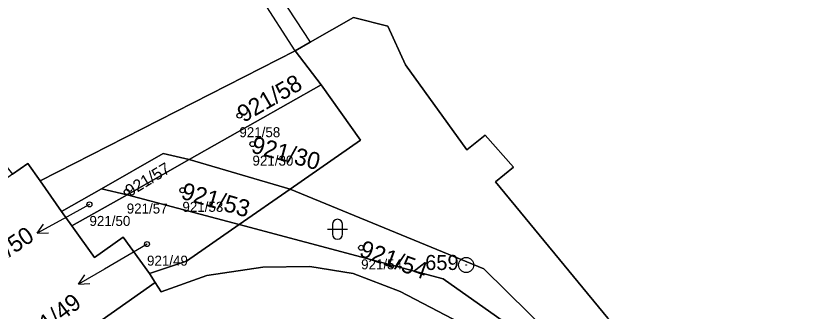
# Model space of a CAD drawing. Extents: x -734504 to -730695, y -1027923 to -1024502.
# Drawn here: x -732714.1 to -732634.2, y -1025598.7 to -1025569.2 of the extents above; entities that cross this region are included whole.
import ezdxf

# ---------------------------------------------------------------- set-up
doc = ezdxf.new("R2010")
doc.units = 0
for name, color, linetype in [('Definiční body', 7, 'Continuous'), ('Hranice parcel', 7, 'Continuous'), ('Parcelní čísla', 7, 'Continuous'), ('Polygon budovy', 7, 'Continuous'), ('Polygon parcely', 7, 'Continuous'), ('Pop  PČ popisy', 7, 'Continuous'), ('Vnitřní kresba', 7, 'Continuous'), ('Značky bodu BP', 7, 'Continuous'), ('Značky kultur', 7, 'Continuous')]:
    doc.layers.add(name, color=color, linetype=linetype)

msp = doc.modelspace()

# ---------------------------------------------------------------- linework, layer by layer
at = {"layer": 'Definiční body'}
for centre in [(-732691.74, -1025579.15), (-732690.43, -1025581.99), (-732703.01, -1025586.78), (-732697.44, -1025586.61), (-732706.74, -1025588.02), (-732700.98, -1025591.99), (-732679.56, -1025592.36)]:
    msp.add_circle(centre, 0.25, dxfattribs=at)
at = {"layer": 'Hranice parcel'}
for p, q in [((-732711.67, -1025585.67), (-732686.15, -1025572.66)), ((-732686.15, -1025572.66), (-732683.56, -1025576.08)), ((-732683.56, -1025576.08), (-732696.75, -1025583.54)), ((-732683.56, -1025576.08), (-732679.63, -1025581.59)), ((-732679.63, -1025581.59), (-732686.67, -1025586.49)), ((-732696.75, -1025583.54), (-732702.98, -1025587.06)), ((-732696.75, -1025583.54), (-732686.67, -1025586.49)), ((-732709.52, -1025588.73), (-732711.67, -1025585.67)), ((-732705.55, -1025586.47), (-732709.52, -1025588.73)), ((-732702.98, -1025587.06), (-732705.55, -1025586.47)), ((-732691.76, -1025590.03), (-732686.67, -1025586.49)), ((-732708.5, -1025590.18), (-732702.98, -1025587.06)), ((-732691.76, -1025590.03), (-732702.98, -1025587.06)), ((-732708.5, -1025590.18), (-732709.52, -1025588.73)), ((-732697.02, -1025593.69), (-732691.76, -1025590.03)), ((-732700.74, -1025594.94), (-732697.02, -1025593.69)), ((-732700.18, -1025595.82), (-732700.74, -1025594.94)), ((-732775.28, -1025648.7), (-732700.18, -1025595.82))]:
    msp.add_line(p, q, dxfattribs=at)
for points in [[(-732686.15, -1025572.66), (-732684.67, -1025571.82), (-732680.32, -1025569.35), (-732676.89, -1025570.22), (-732675.11, -1025574.06), (-732668.99, -1025582.57), (-732667.16, -1025581.11), (-732664.3, -1025584.29), (-732666.13, -1025585.76), (-732654.88, -1025599.38), (-732643.39, -1025610.29), (-732624.66, -1025624.98), (-732610.33, -1025634.78), (-732608.94, -1025635.73)], [(-732696.75, -1025583.54), (-732699.36, -1025582.94), (-732705.55, -1025586.47)], [(-732711.67, -1025585.67), (-732712.9, -1025583.92), (-732714.45, -1025585.01)], [(-732686.67, -1025586.49), (-732667.27, -1025594.47), (-732658.17, -1025603.44), (-732649.45, -1025610.94)], [(-732649.45, -1025610.94), (-732671.35, -1025595.46), (-732691.76, -1025590.03)], [(-732700.74, -1025594.94), (-732703.38, -1025591.3), (-732706.25, -1025593.32), (-732708.5, -1025590.18)], [(-732700.18, -1025595.82), (-732699.57, -1025596.77), (-732694.98, -1025595.14), (-732689.38, -1025594.31), (-732684.7, -1025594.24), (-732680.37, -1025594.93), (-732675.64, -1025596.73), (-732668.11, -1025600.67), (-732662, -1025605.68), (-732654.15, -1025612.63), (-732649.19, -1025617.74), (-732629.12, -1025625.96)]]:
    msp.add_lwpolyline(points, dxfattribs=at)
at = {"layer": 'Polygon budovy'}
msp.add_lwpolyline([(-732712.9, -1025583.92), (-732714.45, -1025585.01), (-732722.24, -1025590.5), (-732723.74, -1025591.59), (-732737.93, -1025601.49), (-732742.43, -1025604.6), (-732785.12, -1025634.61), (-732775.28, -1025648.7), (-732700.18, -1025595.82), (-732700.74, -1025594.94), (-732703.38, -1025591.3), (-732706.25, -1025593.32), (-732708.5, -1025590.18), (-732709.52, -1025588.73), (-732711.67, -1025585.67)], close=True, dxfattribs=at)
at = {"layer": 'Polygon parcely'}
for points in [[(-732775.28, -1025648.7), (-732700.18, -1025595.82), (-732700.74, -1025594.94), (-732703.38, -1025591.3), (-732706.25, -1025593.32), (-732708.5, -1025590.18), (-732709.52, -1025588.73), (-732711.67, -1025585.67), (-732712.9, -1025583.92), (-732714.45, -1025585.01), (-732722.24, -1025590.5), (-732724.62, -1025586.99), (-732723.76, -1025586.02), (-732733.33, -1025572.49), (-732734.01, -1025573.7), (-732735.5, -1025574.81), (-732742.4, -1025566.93), (-732745.02, -1025569.22), (-732756.17, -1025555.67)], [(-732736.32, -1025565.86), (-732719.71, -1025578.43), (-732714.45, -1025585.01), (-732712.9, -1025583.92), (-732711.67, -1025585.67), (-732686.15, -1025572.66), (-732684.67, -1025571.82), (-732680.32, -1025569.35), (-732676.89, -1025570.22), (-732675.11, -1025574.06), (-732668.99, -1025582.57), (-732667.16, -1025581.11), (-732664.3, -1025584.29), (-732666.13, -1025585.76), (-732654.88, -1025599.38), (-732643.39, -1025610.29), (-732624.66, -1025624.98)], [(-732622.42, -1025644.72), (-732637.66, -1025637.7), (-732629.12, -1025625.96), (-732649.19, -1025617.74), (-732654.15, -1025612.63), (-732662, -1025605.68), (-732668.11, -1025600.67), (-732675.64, -1025596.73), (-732680.37, -1025594.93), (-732684.7, -1025594.24), (-732689.38, -1025594.31), (-732694.98, -1025595.14), (-732699.57, -1025596.77), (-732700.18, -1025595.82), (-732775.28, -1025648.7)]]:
    msp.add_lwpolyline(points, dxfattribs=at)
for points in [[(-732629.12, -1025625.96), (-732637.66, -1025637.7), (-732622.42, -1025644.72), (-732614.33, -1025637.51), (-732608.94, -1025635.73), (-732610.33, -1025634.78), (-732624.66, -1025624.98), (-732643.39, -1025610.29), (-732654.88, -1025599.38), (-732666.13, -1025585.76), (-732664.3, -1025584.29), (-732667.16, -1025581.11), (-732668.99, -1025582.57), (-732675.11, -1025574.06), (-732676.89, -1025570.22), (-732680.32, -1025569.35), (-732684.67, -1025571.82), (-732686.15, -1025572.66), (-732683.56, -1025576.08), (-732679.63, -1025581.59), (-732686.67, -1025586.49), (-732667.27, -1025594.47), (-732658.17, -1025603.44), (-732649.45, -1025610.94)], [(-732711.67, -1025585.67), (-732709.52, -1025588.73), (-732705.55, -1025586.47), (-732699.36, -1025582.94), (-732696.75, -1025583.54), (-732683.56, -1025576.08), (-732686.15, -1025572.66)], [(-732696.75, -1025583.54), (-732686.67, -1025586.49), (-732679.63, -1025581.59), (-732683.56, -1025576.08)], [(-732705.55, -1025586.47), (-732702.98, -1025587.06), (-732696.75, -1025583.54), (-732699.36, -1025582.94)], [(-732696.75, -1025583.54), (-732702.98, -1025587.06), (-732691.76, -1025590.03), (-732686.67, -1025586.49)], [(-732709.52, -1025588.73), (-732708.5, -1025590.18), (-732702.98, -1025587.06), (-732705.55, -1025586.47)], [(-732649.45, -1025610.94), (-732658.17, -1025603.44), (-732667.27, -1025594.47), (-732686.67, -1025586.49), (-732691.76, -1025590.03), (-732671.35, -1025595.46)], [(-732691.76, -1025590.03), (-732702.98, -1025587.06), (-732708.5, -1025590.18), (-732706.25, -1025593.32), (-732703.38, -1025591.3), (-732700.74, -1025594.94), (-732697.02, -1025593.69)], [(-732694.98, -1025595.14), (-732689.38, -1025594.31), (-732684.7, -1025594.24), (-732680.37, -1025594.93), (-732675.64, -1025596.73), (-732668.11, -1025600.67), (-732662, -1025605.68), (-732654.15, -1025612.63), (-732649.19, -1025617.74), (-732629.12, -1025625.96), (-732649.45, -1025610.94), (-732671.35, -1025595.46), (-732691.76, -1025590.03), (-732697.02, -1025593.69), (-732700.74, -1025594.94), (-732700.18, -1025595.82), (-732699.57, -1025596.77)]]:
    msp.add_lwpolyline(points, close=True, dxfattribs=at)
at = {"layer": 'Pop  PČ popisy'}
for p, q in [((-732706.74, -1025588.02), (-732709.34, -1025589.46)), ((-732709.34, -1025589.46), (-732711.965, -1025590.915)), ((-732711.965, -1025590.915), (-732711.332, -1025589.991)), ((-732711.965, -1025590.915), (-732710.846, -1025590.867)), ((-732700.98, -1025591.99), (-732705.23, -1025594.49)), ((-732705.23, -1025594.49), (-732707.829, -1025595.99)), ((-732707.829, -1025595.99), (-732707.212, -1025595.056)), ((-732707.829, -1025595.99), (-732706.711, -1025595.923))]:
    msp.add_line(p, q, dxfattribs=at)
at = {"layer": 'Vnitřní kresba'}
for p, q in [((-732707.85, -1025535.96), (-732684.67, -1025571.82)), ((-732686.15, -1025572.66), (-732709.15, -1025536.92))]:
    msp.add_line(p, q, dxfattribs=at)
at = {"layer": 'Značky bodu BP'}
for radius in [0.75, 0.03]:
    msp.add_circle((-732669.05, -1025594.08), radius, dxfattribs=at)
at = {"layer": 'Značky kultur'}
for p, q in [((-732682.421, -1025590.011), (-732682.421, -1025591.012)), ((-732681.419, -1025591.012), (-732681.419, -1025590.011)), ((-732682.921, -1025590.511), (-732680.919, -1025590.511))]:
    msp.add_line(p, q, dxfattribs=at)
for centre, start, end in [((-732681.92, -1025590.011), 0, 180), ((-732681.92, -1025591.011), 180, 359.98789)]:
    msp.add_arc(centre, 0.5, start, end, dxfattribs=at)

# ---------------------------------------------------------------- texts
at = {"layer": 'Definiční body'}
for s, p in [('921/58', (-732691.74, -1025581.306)), ('921/30', (-732690.43, -1025584.146)), ('921/53', (-732697.44, -1025588.766)), ('921/57', (-732703.01, -1025588.936)), ('921/50', (-732706.74, -1025590.176)), ('921/49', (-732700.98, -1025594.146)), ('921/54', (-732679.56, -1025594.516))]:
    msp.add_text(s, height=1, dxfattribs=at).set_placement(p)
at = {"layer": 'Parcelní čísla'}
for s, height, rotation, p in [('921/58', 1.7, 30, (-732691.315, -1025579.886)), ('921/30', 1.7, 345, (-732690.649, -1025582.811)), ('921/57', 1.19, 31, (-732702.703, -1025587.29)), ('921/53', 1.7, 344, (-732697.674, -1025587.427)), ('921/50', 1.7, 34, (-732717.896, -1025595.426)), ('921/54', 1.7, 340, (-732679.85, -1025593.158)), ('921/49', 1.7, 37, (-732712.965, -1025602.341))]:
    msp.add_text(s, height=height, rotation=rotation, dxfattribs=at).set_placement(p)
at = {"layer": 'Značky bodu BP'}
msp.add_text('659', height=1.5, dxfattribs=at).set_placement((-732673.153, -1025594.58))

doc.saveas('drawing.dxf')
